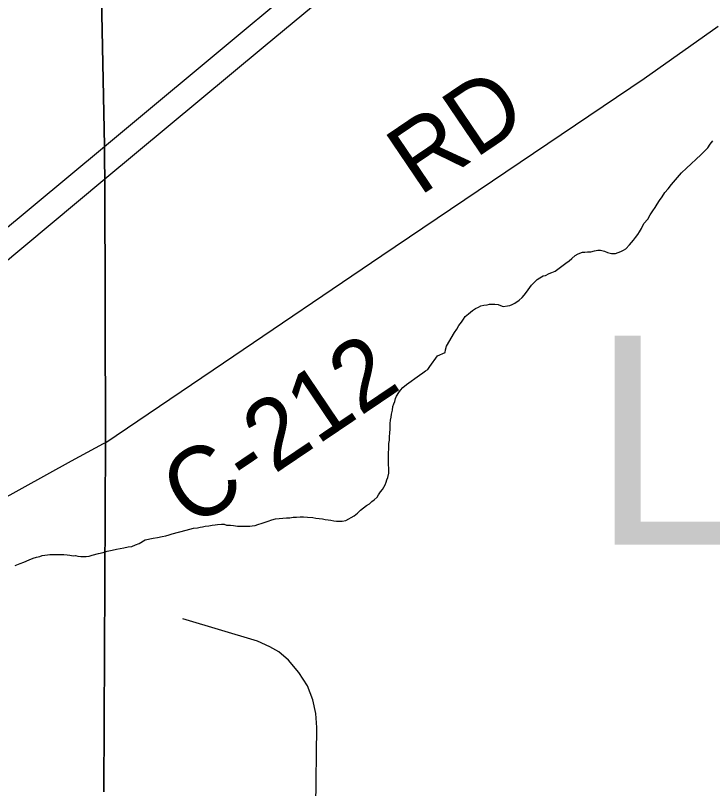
# Model space of a CAD drawing. Extents: x -59 to 82, y -3 to 49.
# Drawn here: x -50.627 to -50.058, y 43.939 to 44.569 of the extents above; entities that cross this region are included whole.
import ezdxf

# ---------------------------------------------------------------- set-up
doc = ezdxf.new("R2010")
doc.units = 0
for name, color, linetype in [('GM_X_Corporation', 7, 'Continuous'), ('GM_X_County_Road', 7, 'Continuous'), ('GM_X_County_Road_Text', 7, 'Continuous'), ('GM_X_Interstate_Route', 7, 'Continuous'), ('GM_X_Minor_River', 7, 'Continuous'), ('GM_X_Township_Road', 7, 'Continuous'), ('SH_Data', 7, 'Continuous')]:
    doc.layers.add(name, color=color, linetype=linetype)

msp = doc.modelspace()

# ---------------------------------------------------------------- linework, layer by layer
at = {"layer": 'GM_X_Corporation'}
for p, q in [((-50.55419, 44.46315), (-50.56664, 45.12717)), ((-50.56664, 45.12717), (-50.55419, 44.46315)), ((-50.55396, 44.4511), (-50.55419, 44.46315)), ((-50.55419, 44.46315), (-50.55396, 44.4511)), ((-50.55392, 44.4366), (-50.55396, 44.4511)), ((-50.55396, 44.4511), (-50.55392, 44.4366)), ((-50.55326, 44.22179), (-50.55392, 44.4366)), ((-50.55392, 44.4366), (-50.55326, 44.22179)), ((-50.55461, 43.9364), (-50.55326, 44.22179)), ((-50.55326, 44.22179), (-50.55461, 43.9364))]:
    msp.add_line(p, q, dxfattribs=at)
at = {"layer": 'GM_X_County_Road'}
for p, q in [((-50.11383, 44.51791), (-50.05354, 44.56071)), ((-50.32788, 44.37367), (-50.11383, 44.51791)), ((-50.45704, 44.28614), (-50.32788, 44.37367)), ((-50.55306, 44.22123), (-50.45704, 44.28614)), ((-50.55485, 44.22027), (-50.55306, 44.22123)), ((-50.58092, 44.20632), (-50.55485, 44.22027)), ((-50.68352, 44.14948), (-50.58092, 44.20632))]:
    msp.add_line(p, q, dxfattribs=at)
at = {"layer": 'GM_X_Interstate_Route'}
for p, q in [((-50.43678, 44.56021), (-49.85224, 45.04605)), ((-50.42467, 44.54349), (-49.9018, 44.97761)), ((-50.55398, 44.46259), (-50.43678, 44.56021)), ((-50.55371, 44.43604), (-50.42467, 44.54349)), ((-50.7008, 44.34066), (-50.55398, 44.46259)), ((-50.6887, 44.32394), (-50.55371, 44.43604))]:
    msp.add_line(p, q, dxfattribs=at)
at = {"layer": 'GM_X_Minor_River'}
for p, q in [((-50.06015, 44.46445), (-50.0579, 44.46713)), ((-50.06467, 44.45871), (-50.06203, 44.46139)), ((-50.06203, 44.46139), (-50.06015, 44.46445)), ((-50.07936, 44.44492), (-50.06768, 44.45565)), ((-50.06768, 44.45565), (-50.06467, 44.45871)), ((-50.0884, 44.43536), (-50.08351, 44.44109)), ((-50.08351, 44.44109), (-50.07936, 44.44492)), ((-50.09179, 44.43153), (-50.0884, 44.43536)), ((-50.09442, 44.42809), (-50.09179, 44.43153)), ((-50.0993, 44.42159), (-50.09705, 44.42503)), ((-50.09705, 44.42503), (-50.09442, 44.42809)), ((-50.10343, 44.41549), (-50.10155, 44.41854)), ((-50.10155, 44.41854), (-50.0993, 44.42159)), ((-50.10905, 44.4067), (-50.1068, 44.41014)), ((-50.1068, 44.41014), (-50.10493, 44.41281)), ((-50.10493, 44.41281), (-50.10343, 44.41549)), ((-50.11431, 44.39982), (-50.11092, 44.40327)), ((-50.11092, 44.40327), (-50.10905, 44.4067)), ((-50.11618, 44.39563), (-50.11431, 44.39982)), ((-50.12106, 44.38837), (-50.11918, 44.39066)), ((-50.11918, 44.39066), (-50.11768, 44.39295)), ((-50.11768, 44.39295), (-50.11618, 44.39563)), ((-50.12594, 44.38225), (-50.12256, 44.38608)), ((-50.12256, 44.38608), (-50.12106, 44.38837)), ((-50.13311, 44.37688), (-50.13085, 44.37803)), ((-50.13085, 44.37803), (-50.12896, 44.37919)), ((-50.12896, 44.37919), (-50.12594, 44.38225)), ((-50.17294, 44.37128), (-50.1703, 44.37358)), ((-50.1703, 44.37358), (-50.16765, 44.37512)), ((-50.16765, 44.37512), (-50.16425, 44.37628)), ((-50.16425, 44.37628), (-50.16235, 44.3763)), ((-50.16235, 44.3763), (-50.16008, 44.37669)), ((-50.16008, 44.37669), (-50.15742, 44.37671)), ((-50.15742, 44.37671), (-50.15439, 44.37749)), ((-50.15439, 44.37749), (-50.15173, 44.37789)), ((-50.15173, 44.37789), (-50.14945, 44.3779)), ((-50.14945, 44.3779), (-50.14641, 44.37717)), ((-50.14641, 44.37717), (-50.14374, 44.37605)), ((-50.14374, 44.37605), (-50.1407, 44.37531)), ((-50.1407, 44.37531), (-50.13728, 44.37533)), ((-50.13728, 44.37533), (-50.13311, 44.37688)), ((-50.18653, 44.36092), (-50.17785, 44.36744)), ((-50.17785, 44.36744), (-50.1752, 44.36936)), ((-50.1752, 44.36936), (-50.17294, 44.37128)), ((-50.19145, 44.35899), (-50.18918, 44.35976)), ((-50.18918, 44.35976), (-50.18653, 44.36092)), ((-50.20354, 44.35168), (-50.20128, 44.35397)), ((-50.20128, 44.35397), (-50.19901, 44.35551)), ((-50.19901, 44.35551), (-50.19637, 44.35705)), ((-50.19637, 44.35705), (-50.19447, 44.35744)), ((-50.19447, 44.35744), (-50.19145, 44.35899)), ((-50.20843, 44.34556), (-50.2058, 44.34938)), ((-50.2058, 44.34938), (-50.20354, 44.35168)), ((-50.21332, 44.33944), (-50.21181, 44.34135)), ((-50.21181, 44.34135), (-50.20993, 44.34365)), ((-50.20993, 44.34365), (-50.20843, 44.34556)), ((-50.24213, 44.33354), (-50.24023, 44.33393)), ((-50.24023, 44.33393), (-50.23795, 44.33395)), ((-50.23795, 44.33395), (-50.23568, 44.33396)), ((-50.23568, 44.33396), (-50.23301, 44.3336)), ((-50.22162, 44.33368), (-50.21935, 44.33484)), ((-50.21935, 44.33484), (-50.21596, 44.33714)), ((-50.21596, 44.33714), (-50.21332, 44.33944)), ((-50.25726, 44.32621), (-50.25386, 44.3289)), ((-50.25386, 44.3289), (-50.2516, 44.33043)), ((-50.2516, 44.33043), (-50.24895, 44.33159)), ((-50.24895, 44.33159), (-50.24706, 44.33274)), ((-50.24706, 44.33274), (-50.24478, 44.33314)), ((-50.24478, 44.33314), (-50.24213, 44.33354)), ((-50.23301, 44.3336), (-50.23111, 44.33285)), ((-50.23111, 44.33285), (-50.22883, 44.33211)), ((-50.22883, 44.33211), (-50.22541, 44.33252)), ((-50.22541, 44.33252), (-50.22351, 44.33291)), ((-50.22351, 44.33291), (-50.22162, 44.33368)), ((-50.2629, 44.31933), (-50.2614, 44.32162)), ((-50.2614, 44.32162), (-50.2599, 44.32391)), ((-50.2599, 44.32391), (-50.25726, 44.32621)), ((-50.26665, 44.3136), (-50.26515, 44.31665)), ((-50.26515, 44.31665), (-50.2629, 44.31933)), ((-50.27527, 44.29985), (-50.26853, 44.31092)), ((-50.26853, 44.31092), (-50.26665, 44.3136)), ((-50.27637, 44.29452), (-50.27601, 44.29681)), ((-50.27601, 44.29681), (-50.27527, 44.29985)), ((-50.2888, 44.28303), (-50.28242, 44.29182)), ((-50.28242, 44.29182), (-50.27637, 44.29452)), ((-50.29711, 44.27613), (-50.29446, 44.27805)), ((-50.29446, 44.27805), (-50.2922, 44.27958)), ((-50.2922, 44.27958), (-50.29031, 44.28074)), ((-50.29031, 44.28074), (-50.2888, 44.28303)), ((-50.30768, 44.26845), (-50.29711, 44.27613)), ((-50.31257, 44.26385), (-50.31069, 44.26615)), ((-50.31069, 44.26615), (-50.30768, 44.26845)), ((-50.3167, 44.25698), (-50.31595, 44.25889)), ((-50.31595, 44.25889), (-50.31408, 44.26194)), ((-50.31408, 44.26194), (-50.31257, 44.26385)), ((-50.31892, 44.2505), (-50.31818, 44.25279)), ((-50.31818, 44.25279), (-50.31743, 44.25469)), ((-50.31743, 44.25469), (-50.3167, 44.25698)), ((-50.32001, 44.24441), (-50.31928, 44.24746)), ((-50.31928, 44.24746), (-50.31892, 44.2505)), ((-50.32109, 44.2368), (-50.32073, 44.23946)), ((-50.32073, 44.23946), (-50.32037, 44.24175)), ((-50.32037, 44.24175), (-50.32001, 44.24441)), ((-50.32107, 44.2349), (-50.32109, 44.2368)), ((-50.32105, 44.23224), (-50.32107, 44.2349)), ((-50.32176, 44.22615), (-50.3214, 44.22881)), ((-50.3214, 44.22881), (-50.32105, 44.23224)), ((-50.3221, 44.22044), (-50.32174, 44.22311)), ((-50.32208, 44.21778), (-50.3221, 44.22044)), ((-50.32174, 44.22311), (-50.32176, 44.22615)), ((-50.32242, 44.21321), (-50.32206, 44.2155)), ((-50.32206, 44.2155), (-50.32208, 44.21778)), ((-50.32239, 44.21017), (-50.32242, 44.21321)), ((-50.32237, 44.20675), (-50.32239, 44.21017)), ((-50.32234, 44.20333), (-50.32237, 44.20675)), ((-50.32231, 44.19991), (-50.32234, 44.20333)), ((-50.32301, 44.19268), (-50.32228, 44.19611)), ((-50.32228, 44.19611), (-50.32231, 44.19991)), ((-50.3245, 44.18887), (-50.32376, 44.19077)), ((-50.32376, 44.19077), (-50.32301, 44.19268)), ((-50.32899, 44.18085), (-50.32749, 44.18276)), ((-50.32749, 44.18276), (-50.32524, 44.18658)), ((-50.32524, 44.18658), (-50.3245, 44.18887)), ((-50.33426, 44.17435), (-50.33162, 44.17665)), ((-50.33162, 44.17665), (-50.33049, 44.17856)), ((-50.33049, 44.17856), (-50.32899, 44.18085)), ((-50.34029, 44.16974), (-50.33803, 44.17128)), ((-50.33803, 44.17128), (-50.33615, 44.1732)), ((-50.33615, 44.1732), (-50.33426, 44.17435)), ((-50.34784, 44.16361), (-50.3452, 44.16591)), ((-50.3452, 44.16591), (-50.34294, 44.16783)), ((-50.34294, 44.16783), (-50.34029, 44.16974)), ((-50.42069, 44.15702), (-50.41766, 44.15818)), ((-50.41766, 44.15818), (-50.41463, 44.15896)), ((-50.41463, 44.15896), (-50.4116, 44.15936)), ((-50.4116, 44.15936), (-50.40856, 44.15938)), ((-50.40856, 44.15938), (-50.40553, 44.15979)), ((-50.40553, 44.15979), (-50.40287, 44.15981)), ((-50.40287, 44.15981), (-50.40021, 44.1602)), ((-50.40021, 44.1602), (-50.39756, 44.16022)), ((-50.39756, 44.16022), (-50.39452, 44.16062)), ((-50.39452, 44.16062), (-50.39186, 44.16064)), ((-50.39186, 44.16064), (-50.38844, 44.16029)), ((-50.38844, 44.16029), (-50.38426, 44.15993)), ((-50.38426, 44.15993), (-50.3816, 44.15957)), ((-50.3816, 44.15957), (-50.37894, 44.15921)), ((-50.37894, 44.15921), (-50.37628, 44.15885)), ((-50.37628, 44.15885), (-50.374, 44.15849)), ((-50.374, 44.15849), (-50.37172, 44.15812)), ((-50.37172, 44.15812), (-50.36944, 44.15776)), ((-50.36944, 44.15776), (-50.36716, 44.15739)), ((-50.36032, 44.15706), (-50.35728, 44.15746)), ((-50.35728, 44.15746), (-50.35048, 44.16131)), ((-50.35048, 44.16131), (-50.34784, 44.16361)), ((-50.48443, 44.15049), (-50.4814, 44.15127)), ((-50.4814, 44.15127), (-50.47837, 44.15168)), ((-50.47837, 44.15168), (-50.47609, 44.15207)), ((-50.47609, 44.15207), (-50.4742, 44.15247)), ((-50.4742, 44.15247), (-50.47192, 44.15286)), ((-50.47192, 44.15286), (-50.46889, 44.15326)), ((-50.46889, 44.15326), (-50.46623, 44.15366)), ((-50.46623, 44.15366), (-50.46396, 44.15406)), ((-50.46396, 44.15406), (-50.46206, 44.15445)), ((-50.46206, 44.15445), (-50.45865, 44.15448)), ((-50.45865, 44.15448), (-50.45637, 44.15449)), ((-50.45637, 44.15449), (-50.45446, 44.15374)), ((-50.45446, 44.15374), (-50.45143, 44.15377)), ((-50.45143, 44.15377), (-50.44876, 44.1534)), ((-50.44876, 44.1534), (-50.44572, 44.15304)), ((-50.44572, 44.15304), (-50.44307, 44.15306)), ((-50.44307, 44.15306), (-50.44041, 44.15308)), ((-50.44041, 44.15308), (-50.43813, 44.1531)), ((-50.43813, 44.1531), (-50.43547, 44.15311)), ((-50.43547, 44.15311), (-50.43357, 44.15313)), ((-50.43357, 44.15313), (-50.4313, 44.15352)), ((-50.4313, 44.15352), (-50.42903, 44.1543)), ((-50.42903, 44.1543), (-50.42562, 44.15546)), ((-50.42562, 44.15546), (-50.42069, 44.15702)), ((-50.36716, 44.15739), (-50.36487, 44.15703)), ((-50.36487, 44.15703), (-50.3626, 44.15704)), ((-50.3626, 44.15704), (-50.36032, 44.15706)), ((-50.50717, 44.14463), (-50.50414, 44.14503)), ((-50.50414, 44.14503), (-50.50148, 44.14581)), ((-50.50148, 44.14581), (-50.49883, 44.14659)), ((-50.49883, 44.14659), (-50.48747, 44.14971)), ((-50.48747, 44.14971), (-50.48443, 44.15049)), ((-50.52876, 44.13764), (-50.52573, 44.1388)), ((-50.52573, 44.1388), (-50.52082, 44.14188)), ((-50.52082, 44.14188), (-50.51437, 44.14306)), ((-50.51437, 44.14306), (-50.51096, 44.14385)), ((-50.51096, 44.14385), (-50.50717, 44.14463)), ((-50.55529, 44.13137), (-50.55188, 44.13253)), ((-50.55188, 44.13253), (-50.54771, 44.13332)), ((-50.54771, 44.13332), (-50.5443, 44.13411)), ((-50.5443, 44.13411), (-50.54127, 44.13489)), ((-50.54127, 44.13489), (-50.53823, 44.13529)), ((-50.53823, 44.13529), (-50.53482, 44.13607)), ((-50.53482, 44.13607), (-50.53179, 44.13648)), ((-50.53179, 44.13648), (-50.52876, 44.13764)), ((-50.61562, 44.12563), (-50.61221, 44.12679)), ((-50.61221, 44.12679), (-50.60956, 44.12757)), ((-50.60956, 44.12757), (-50.60691, 44.12835)), ((-50.60691, 44.12835), (-50.60501, 44.12913)), ((-50.60501, 44.12913), (-50.60046, 44.12953)), ((-50.60046, 44.12953), (-50.59857, 44.12993)), ((-50.59857, 44.12993), (-50.59667, 44.12994)), ((-50.59667, 44.12994), (-50.59287, 44.12997)), ((-50.59287, 44.12997), (-50.59021, 44.12999)), ((-50.59021, 44.12999), (-50.58718, 44.13001)), ((-50.58718, 44.13001), (-50.58451, 44.12965)), ((-50.58451, 44.12965), (-50.58223, 44.12928)), ((-50.58223, 44.12928), (-50.57957, 44.12892)), ((-50.57957, 44.12892), (-50.57767, 44.12893)), ((-50.57767, 44.12893), (-50.57577, 44.12857)), ((-50.57577, 44.12857), (-50.57349, 44.1282)), ((-50.57349, 44.1282), (-50.57083, 44.12822)), ((-50.57083, 44.12822), (-50.56893, 44.12823)), ((-50.56893, 44.12823), (-50.56666, 44.12863)), ((-50.56666, 44.12863), (-50.56401, 44.12941)), ((-50.56401, 44.12941), (-50.55908, 44.13058)), ((-50.55908, 44.13058), (-50.55529, 44.13137)), ((-50.62697, 44.12099), (-50.62281, 44.12254)), ((-50.62281, 44.12254), (-50.61978, 44.1237)), ((-50.61978, 44.1237), (-50.61562, 44.12563))]:
    msp.add_line(p, q, dxfattribs=at)
at = {"layer": 'GM_X_Township_Road'}
for p, q in [((-50.42918, 44.05931), (-50.49024, 44.07748)), ((-50.41929, 44.05463), (-50.42918, 44.05931)), ((-50.41187, 44.05051), (-50.41929, 44.05463)), ((-50.4039, 44.04364), (-50.41187, 44.05051)), ((-50.39565, 44.03374), (-50.4039, 44.04364)), ((-50.3885, 44.02275), (-50.39565, 44.03374)), ((-50.3841, 44.01148), (-50.3885, 44.02275)), ((-50.38163, 44.00021), (-50.3841, 44.01148)), ((-50.38081, 43.98894), (-50.38163, 44.00021)), ((-50.38246, 43.87185), (-50.38081, 43.98894))]:
    msp.add_line(p, q, dxfattribs=at)

# ---------------------------------------------------------------- texts
at = {"layer": 'GM_X_County_Road_Text'}
for s, rotation, p in [('RD', 34.10209, (-50.29737, 44.4214)), ('C-212', 33.99658, (-50.48215, 44.15023))]:
    msp.add_text(s, height=0.056818, rotation=rotation, dxfattribs=at).set_placement(p)
at = {"layer": 'SH_Data'}
msp.add_text('LEROY', height=0.170455, dxfattribs=at).set_placement((-50.15682, 44.13779))

doc.saveas('drawing.dxf')
